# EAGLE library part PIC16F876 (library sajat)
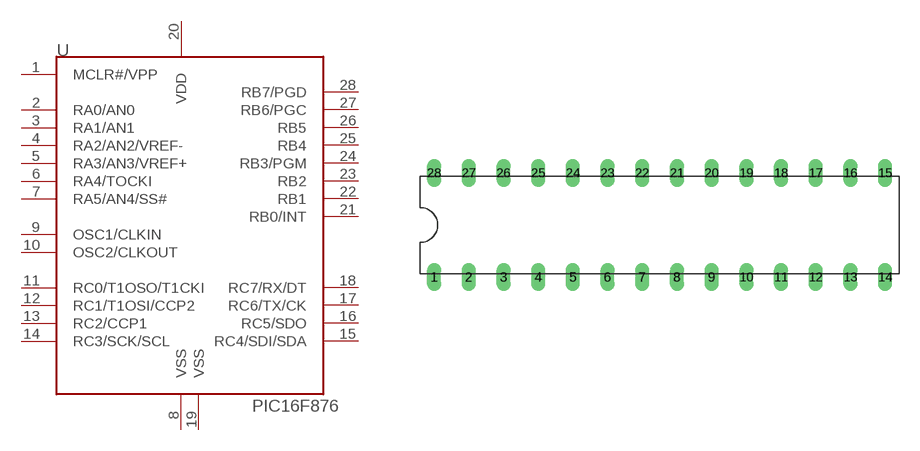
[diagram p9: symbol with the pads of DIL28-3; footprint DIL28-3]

Designator prefix -

## PIC16F876  [DIL28-3]
1  MCLR#/VPP
2  RA0/AN0
3  RA1/AN1
4  RA2/AN2/VREF-
5  RA3/AN3/VREF+
6  RA4/TOCKI
7  RA5/AN4/SS#
8  VSS
9  OSC1/CLKIN
10  OSC2/CLKOUT
11  RC0/T1OSO/T1CKI
12  RC1/T1OSI/CCP2
13  RC2/CCP1
14  RC3/SCK/SCL
15  RC4/SDI/SDA
16  RC5/SDO
17  RC6/TX/CK
18  RC7/RX/DT
19  VSS
20  VDD
21  RB0/INT
22  RB1
23  RB2
24  RB3/PGM
25  RB4
26  RB5
27  RB6/PGC
28  RB7/PGD

## Footprint DIL28-3 (pad centres in mm)
drill 0.3 pad 1.016 long: 1 -16.51,-3.81; 2 -13.97,-3.81; 3 -11.43,-3.81; 4 -8.89,-3.81; 5 -6.35,-3.81; 6 -3.81,-3.81; 7 -1.27,-3.81; 8 1.27,-3.81; 9 3.81,-3.81; 10 6.35,-3.81; 11 8.89,-3.81; 12 11.43,-3.81; 13 13.97,-3.81; 14 16.51,-3.81; 15 16.51,3.81; 16 13.97,3.81; 17 11.43,3.81; 18 8.89,3.81; 19 6.35,3.81; 20 3.81,3.81; 21 1.27,3.81; 22 -1.27,3.81; 23 -3.81,3.81; 24 -6.35,3.81; 25 -8.89,3.81; 26 -11.43,3.81; 27 -13.97,3.81; 28 -16.51,3.81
